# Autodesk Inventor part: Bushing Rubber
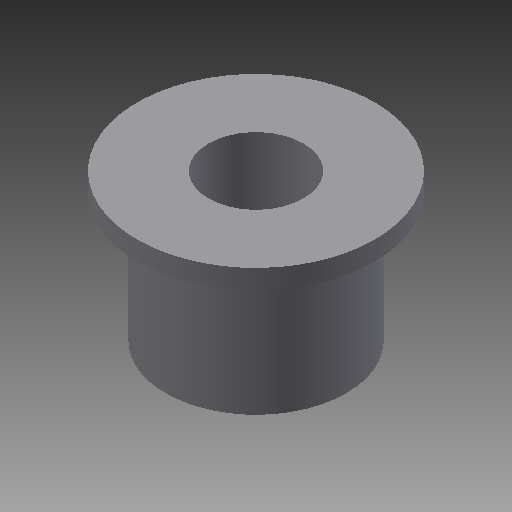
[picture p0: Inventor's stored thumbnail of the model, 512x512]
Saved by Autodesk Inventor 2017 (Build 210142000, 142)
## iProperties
Created: 2010-03
Part Number: Bushing Rubber
Document SubType Name: Modeling
Designer: bhakira
Density: 1 g/cm^3
Material: Generic
Appearance: Default
Author: bhakira
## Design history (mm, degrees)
sketch "Sketch1"
  geometry: L1 (25, 31)-(25, 27); L2 (25, 27)-(19, 27); L3 (19, 27)-(19, 0); L4 (19, 0)-(0, 0); L5 (0, 0)-(0, 31); L6 (0, 31)-(25, 31); 1 further point
  constraints: 12 end point, 1 coincident, 1 other
  dimensions: "d1" = 50 diameter of L1 L5; "d2" = 38 diameter of L3 L5; "d3" = 4 distance of L1.start L1.end; "d4" = 27 distance between parallel lines of L4 L2
revolve "Revolution1" sketch "Sketch1" stored, may be unused: angle "d5" = 90 deg
hole "Hole1" diameter "d8" = 20; stored, may be unused: countersink angle "d12" = 82 deg, drill point angle "d14" = 118 deg; dims "d6" = 10, "d7" = 10, "d9" = 6, "d10" = 34.925, "d11" = 2, "d13" = 8
body "Solid1"
